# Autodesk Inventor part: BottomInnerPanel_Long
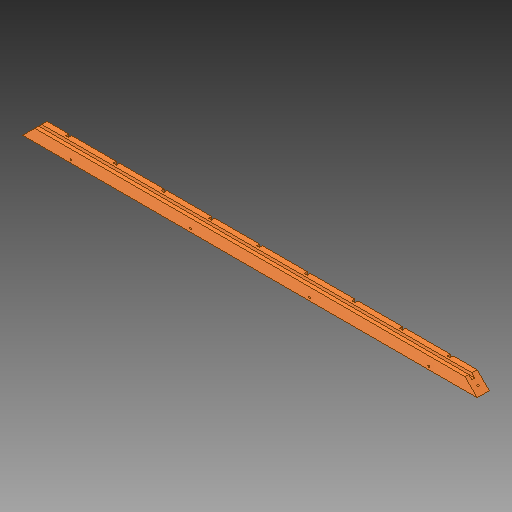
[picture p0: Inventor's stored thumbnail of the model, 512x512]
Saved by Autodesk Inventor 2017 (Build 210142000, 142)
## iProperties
Created: 2017-05
Part Number: BottomInnerPanel_Long
Material: Generic
Document SubType Name: Modeling
Designer: Savy
Density: 1 g/cm^3
Appearance: Default
Mass: 550.247 g
Surface Area: 1112.89 cm^2
Volume: 550.247 cm^3
Author: Savy
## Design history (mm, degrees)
feature "SOLID1"
body "Solid1"
